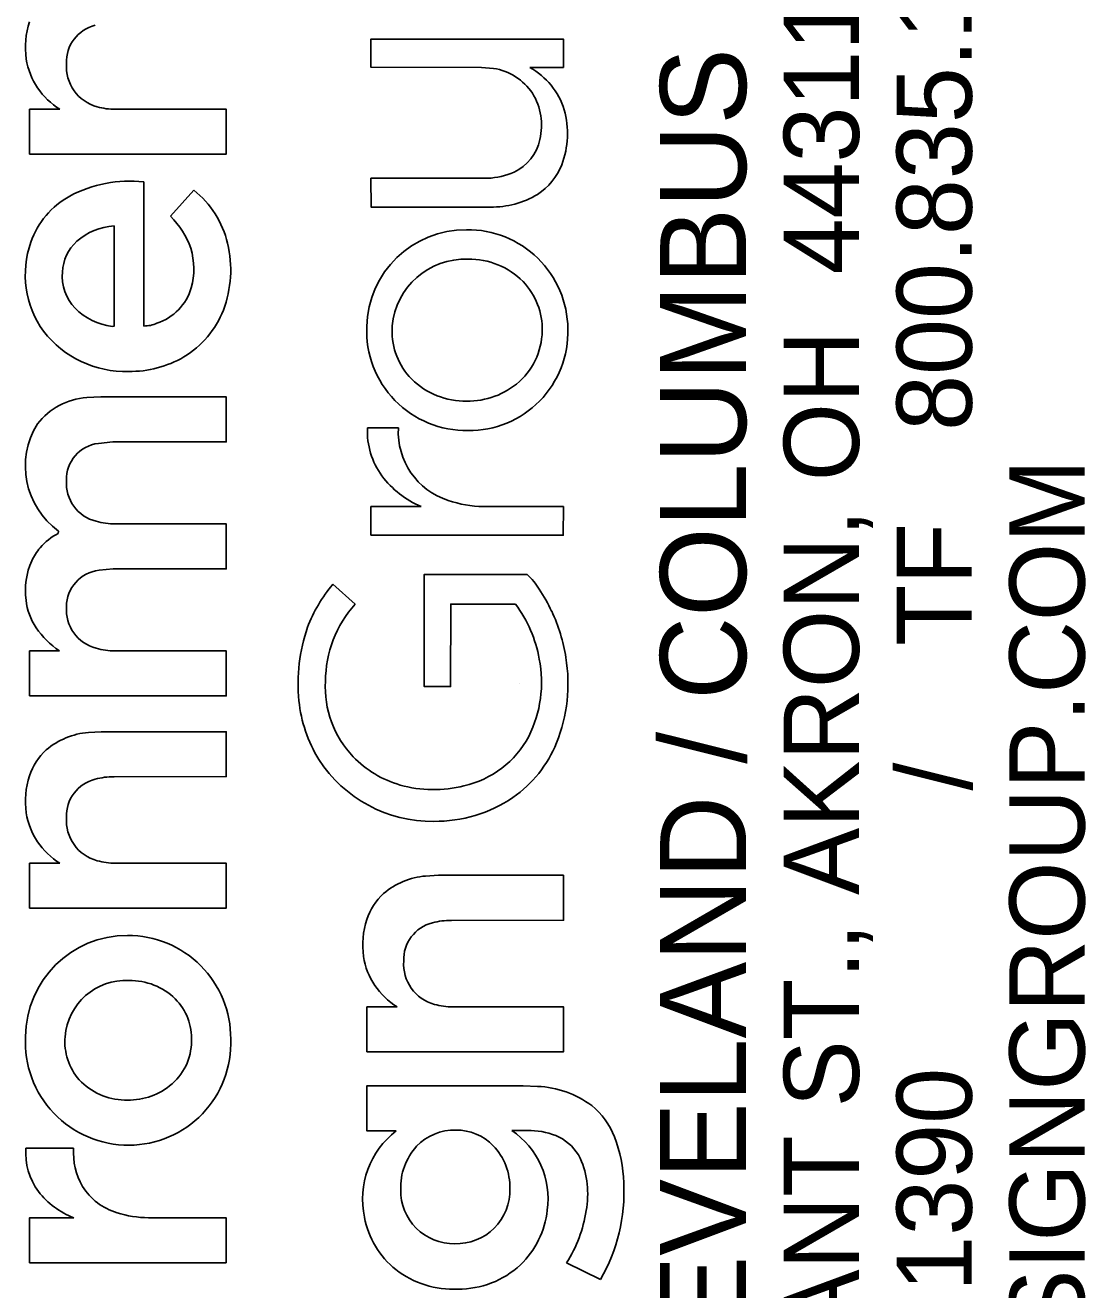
# Model space of a CAD drawing. Extents: x 0 to 34, y 0 to 22.
# Drawn here: x 32.423 to 33.125, y 3.098 to 3.936 of the extents above; entities that cross this region are included whole.
import ezdxf

# ---------------------------------------------------------------- set-up
doc = ezdxf.new("R2010")
doc.units = 0
doc.layers.add('SH_Data', color=7, linetype='Continuous')
doc.layers.add('SH_Text', color=7, linetype='Continuous')

msp = doc.modelspace()

# ---------------------------------------------------------------- linework, layer by layer
at = {"layer": 'SH_Data'}
msp.add_line((32.75, 3.5), (32.75, 3.5), dxfattribs=at)
at = {"layer": 'SH_Text'}
for p, q in [((32.65152, 3.90801), (32.65153, 3.92672)), ((32.65153, 3.92672), (32.7791, 3.92664)), ((32.7791, 3.92664), (32.77908, 3.90796)), ((32.7249, 3.90796), (32.65152, 3.90801)), ((32.7328, 3.90727), (32.7249, 3.90796)), ((32.77908, 3.90796), (32.75689, 3.90796)), ((32.42542, 3.88016), (32.44552, 3.88021)), ((32.42542, 3.85035), (32.42542, 3.88016)), ((32.48222, 3.88021), (32.55569, 3.88021)), ((32.55569, 3.88021), (32.55571, 3.85045)), ((32.55571, 3.85045), (32.42542, 3.85035)), ((32.50108, 3.83209), (32.50118, 3.73657)), ((32.65154, 3.83443), (32.72905, 3.8345)), ((32.65165, 3.81543), (32.65154, 3.83443)), ((32.51882, 3.80927), (32.53422, 3.82662)), ((32.73073, 3.81543), (32.65165, 3.81543)), ((32.48144, 3.73644), (32.48144, 3.80296)), ((32.48016, 3.73628), (32.48144, 3.73644)), ((32.46329, 3.68915), (32.47259, 3.68968)), ((32.47259, 3.68968), (32.55557, 3.68968)), ((32.55557, 3.68968), (32.55571, 3.65982)), ((32.64932, 3.66907), (32.66978, 3.66907)), ((32.48058, 3.65981), (32.47102, 3.65881)), ((32.55571, 3.65982), (32.48058, 3.65981)), ((32.65152, 3.61699), (32.68476, 3.617)), ((32.65152, 3.598), (32.65152, 3.61699)), ((32.72605, 3.61703), (32.7791, 3.61696)), ((32.7791, 3.61696), (32.77903, 3.598)), ((32.48218, 3.60553), (32.55571, 3.60548)), ((32.55571, 3.60548), (32.55571, 3.57568)), ((32.44443, 3.59922), (32.44455, 3.60072)), ((32.77903, 3.598), (32.65152, 3.598)), ((32.4809, 3.57567), (32.47143, 3.57474)), ((32.55571, 3.57568), (32.4809, 3.57567)), ((32.6868, 3.57185), (32.75516, 3.57192)), ((32.6868, 3.49778), (32.6868, 3.57185)), ((32.62636, 3.56548), (32.64114, 3.55241)), ((32.70448, 3.55241), (32.70432, 3.49775)), ((32.74737, 3.55227), (32.70448, 3.55241)), ((32.42542, 3.49152), (32.42545, 3.52138)), ((32.42545, 3.52138), (32.44515, 3.52138)), ((32.48206, 3.52138), (32.55571, 3.52136)), ((32.55571, 3.52136), (32.55571, 3.49156)), ((32.70432, 3.49775), (32.6868, 3.49778)), ((32.55571, 3.49156), (32.42542, 3.49152)), ((32.46439, 3.46736), (32.47289, 3.46783)), ((32.47289, 3.46783), (32.55571, 3.46783)), ((32.55571, 3.46783), (32.55571, 3.43804)), ((32.55571, 3.43804), (32.4814, 3.43796)), ((32.42542, 3.38066), (32.44552, 3.38071)), ((32.42542, 3.35086), (32.42542, 3.38066)), ((32.48222, 3.38071), (32.55569, 3.38071)), ((32.55569, 3.38071), (32.55571, 3.35096)), ((32.68784, 3.3722), (32.69634, 3.37266)), ((32.69634, 3.37266), (32.77916, 3.37266)), ((32.77916, 3.37266), (32.77917, 3.34287)), ((32.55571, 3.35096), (32.42542, 3.35086)), ((32.77917, 3.34287), (32.70485, 3.3428)), ((32.64888, 3.2855), (32.66897, 3.28555)), ((32.64888, 3.25569), (32.64888, 3.2855)), ((32.70568, 3.28555), (32.77915, 3.28555)), ((32.77915, 3.28555), (32.77917, 3.25579)), ((32.77917, 3.25579), (32.64888, 3.25569)), ((32.6489, 3.20336), (32.64889, 3.23322)), ((32.64889, 3.23322), (32.75236, 3.23322)), ((32.75236, 3.23322), (32.76191, 3.23285)), ((32.66836, 3.20336), (32.6489, 3.20336)), ((32.75763, 3.20356), (32.74487, 3.20361)), ((32.42299, 3.19193), (32.45454, 3.19193)), ((32.42542, 3.14577), (32.45473, 3.14579)), ((32.42542, 3.11593), (32.42542, 3.14577)), ((32.50413, 3.14581), (32.55571, 3.14573)), ((32.55571, 3.14573), (32.55565, 3.11593)), ((32.55565, 3.11593), (32.42542, 3.11593)), ((32.8036, 3.10491), (32.7812, 3.11598))]:
    msp.add_line(p, q, dxfattribs=at)
for points in [[(32.7328, 3.90727), (32.7249, 3.90796), (32.65152, 3.90801), (32.65153, 3.92672), (32.7791, 3.92664), (32.77908, 3.90796), (32.75689, 3.90796)], [(32.42542, 3.85035), (32.42542, 3.88016), (32.44552, 3.88021)], [(32.48222, 3.88021), (32.55569, 3.88021), (32.55571, 3.85045), (32.42542, 3.85035)], [(32.50108, 3.83209), (32.50118, 3.73657)], [(32.73073, 3.81543), (32.65165, 3.81543), (32.65154, 3.83443), (32.72905, 3.8345)], [(32.51882, 3.80927), (32.53422, 3.82662)], [(32.48016, 3.73628), (32.48144, 3.73644), (32.48144, 3.80296)], [(32.46329, 3.68915), (32.47259, 3.68968), (32.55557, 3.68968), (32.55571, 3.65982), (32.48058, 3.65981), (32.47102, 3.65881)], [(32.64932, 3.66907), (32.66978, 3.66907)], [(32.72605, 3.61703), (32.7791, 3.61696), (32.77903, 3.598), (32.65152, 3.598)], [(32.65152, 3.598), (32.65152, 3.61699), (32.68476, 3.617)], [(32.48218, 3.60553), (32.55571, 3.60548), (32.55571, 3.57568), (32.4809, 3.57567), (32.47143, 3.57474)], [(32.44443, 3.59922), (32.44455, 3.60072)], [(32.74737, 3.55227), (32.70448, 3.55241), (32.70432, 3.49775), (32.6868, 3.49778), (32.6868, 3.57185), (32.75516, 3.57192)], [(32.62636, 3.56548), (32.64114, 3.55241)], [(32.42542, 3.49152), (32.42545, 3.52138), (32.44515, 3.52138)], [(32.48206, 3.52138), (32.55571, 3.52136), (32.55571, 3.49156), (32.42542, 3.49152)], [(32.46439, 3.46736), (32.47289, 3.46783), (32.55571, 3.46783), (32.55571, 3.43804), (32.4814, 3.43796)], [(32.42542, 3.35086), (32.42542, 3.38066), (32.44552, 3.38071)], [(32.48222, 3.38071), (32.55569, 3.38071), (32.55571, 3.35096), (32.42542, 3.35086)], [(32.68784, 3.3722), (32.69634, 3.37266), (32.77916, 3.37266), (32.77917, 3.34287), (32.70485, 3.3428)], [(32.64888, 3.25569), (32.64888, 3.2855), (32.66897, 3.28555)], [(32.70568, 3.28555), (32.77915, 3.28555), (32.77917, 3.25579), (32.64888, 3.25569)], [(32.66836, 3.20336), (32.6489, 3.20336), (32.64889, 3.23322), (32.75236, 3.23322), (32.76191, 3.23285)], [(32.75763, 3.20356), (32.74487, 3.20361)], [(32.42299, 3.19193), (32.45454, 3.19193)], [(32.50413, 3.14581), (32.55571, 3.14573), (32.55565, 3.11593), (32.42542, 3.11593)], [(32.42542, 3.11593), (32.42542, 3.14577), (32.45473, 3.14579)], [(32.8036, 3.10491), (32.7812, 3.11598)]]:
    msp.add_lwpolyline(points, dxfattribs=at)
for centre, radius, start, end in [((32.47872, 3.92108), 0.05602, 162.27398, 187.79173), ((32.47872, 3.92108), 0.05602, 162.27398, 187.79173), ((32.47482, 3.91155), 0.02498, 103.68683, 182.21395), ((32.47482, 3.91155), 0.02498, 103.68683, 182.21395), ((32.47027, 3.9209), 0.04763, 188.96462, 238.69865), ((32.47027, 3.9209), 0.04763, 188.96462, 238.69865), ((32.47735, 3.90846), 0.02757, 175.58441, 255.13816), ((32.47735, 3.90846), 0.02757, 175.58441, 255.13816), ((32.72711, 3.86998), 0.03772, 33.50082, 81.32954), ((32.72711, 3.86998), 0.03772, 33.50082, 81.32954), ((32.73239, 3.86485), 0.04959, 17.62209, 60.38974), ((32.73239, 3.86485), 0.04959, 17.62209, 60.38974), ((32.72414, 3.8695), 0.04048, 346.56179, 31.75389), ((32.72414, 3.8695), 0.04048, 346.56179, 31.75389), ((32.48183, 3.92235), 0.04215, 254.08913, 270.52838), ((32.48183, 3.92235), 0.04215, 254.08913, 270.52838), ((32.72343, 3.86415), 0.05838, 339.16197, 15.61485), ((32.72343, 3.86415), 0.05838, 339.16197, 15.61485), ((32.73371, 3.86616), 0.03042, 294.63214, 348.48625), ((32.73371, 3.86616), 0.03042, 294.63214, 348.48625), ((32.72747, 3.88081), 0.04633, 271.95199, 294.08943), ((32.72747, 3.88081), 0.04633, 271.95199, 294.08943), ((32.739, 3.85901), 0.04201, 303.10391, 338.15613), ((32.739, 3.85901), 0.04201, 303.10391, 338.15613), ((32.49176, 3.74874), 0.08387, 83.62118, 118.28448), ((32.49176, 3.74874), 0.08387, 83.62118, 118.28448), ((32.47894, 3.77368), 0.05583, 118.82935, 160.62242), ((32.47894, 3.77368), 0.05583, 118.82935, 160.62242), ((32.49399, 3.7763), 0.06443, 13.53275, 51.36266), ((32.49399, 3.7763), 0.06443, 13.53275, 51.36266), ((32.7321, 3.87256), 0.05715, 268.62699, 301.47779), ((32.7321, 3.87256), 0.05715, 268.62699, 301.47779), ((32.48033, 3.77018), 0.05485, 19.0387, 45.44322), ((32.48033, 3.77018), 0.05485, 19.0387, 45.44322), ((32.4844, 3.76071), 0.04236, 94.01311, 130.88062), ((32.4844, 3.76071), 0.04236, 94.01311, 130.88062), ((32.71435, 3.73484), 0.06552, 89.48213, 178.77752), ((32.71435, 3.73484), 0.06552, 89.48213, 178.77752), ((32.71582, 3.73414), 0.06623, 0.42265, 90.7613), ((32.71582, 3.73414), 0.06623, 0.42265, 90.7613), ((32.48697, 3.77074), 0.06438, 160.52138, 215.78155), ((32.48697, 3.77074), 0.06438, 160.52138, 215.78155), ((32.47703, 3.7709), 0.02985, 132.98553, 177.1802), ((32.47703, 3.7709), 0.02985, 132.98553, 177.1802), ((32.48724, 3.77433), 0.04701, 344.60723, 17.00675), ((32.48724, 3.77433), 0.04701, 344.60723, 17.00675), ((32.48289, 3.77384), 0.0758, 339.35431, 13.37708), ((32.48289, 3.77384), 0.0758, 339.35431, 13.37708), ((32.71397, 3.73244), 0.04846, 87.68827, 175.01696), ((32.71397, 3.73244), 0.04846, 87.68827, 175.01696), ((32.71659, 3.73036), 0.05052, 44.91202, 90.75914), ((32.71659, 3.73036), 0.05052, 44.91202, 90.75914), ((32.47824, 3.76966), 0.03114, 175.00138, 223.2876), ((32.47824, 3.76966), 0.03114, 175.00138, 223.2876), ((32.49895, 3.77177), 0.03504, 288.01084, 343.55364), ((32.49895, 3.77177), 0.03504, 288.01084, 343.55364), ((32.71955, 3.73452), 0.04549, 358.32279, 43.83486), ((32.71955, 3.73452), 0.04549, 358.32279, 43.83486), ((32.48546, 3.77826), 0.04232, 225.06454, 262.79701), ((32.48546, 3.77826), 0.04232, 225.06454, 262.79701), ((32.49548, 3.76982), 0.0626, 300.94393, 338.73223), ((32.49548, 3.76982), 0.0626, 300.94393, 338.73223), ((32.50129, 3.75678), 0.02021, 269.70042, 294.87295), ((32.50129, 3.75678), 0.02021, 269.70042, 294.87295), ((32.71483, 3.7334), 0.06606, 177.53728, 270.94524), ((32.71483, 3.7334), 0.06606, 177.53728, 270.94524), ((32.71085, 3.73311), 0.0453, 175.51467, 221.42047), ((32.71085, 3.73311), 0.0453, 175.51467, 221.42047), ((32.48908, 3.77516), 0.06872, 217.74341, 271.65606), ((32.48908, 3.77516), 0.06872, 217.74341, 271.65606), ((32.71671, 3.73271), 0.06536, 269.30834, 1.67905), ((32.71671, 3.73271), 0.06536, 269.30834, 1.67905), ((32.71931, 3.73374), 0.04572, 308.90382, 359.30947), ((32.71931, 3.73374), 0.04572, 308.90382, 359.30947), ((32.49204, 3.77702), 0.07055, 269.20529, 300.33566), ((32.49204, 3.77702), 0.07055, 269.20529, 300.33566), ((32.71399, 3.73734), 0.05046, 222.66255, 268.37331), ((32.71399, 3.73734), 0.05046, 222.66255, 268.37331), ((32.71567, 3.73859), 0.05178, 266.55312, 308.67253), ((32.71567, 3.73859), 0.05178, 266.55312, 308.67253), ((32.46638, 3.64404), 0.04521, 93.91118, 142.30723), ((32.46638, 3.64404), 0.04521, 93.91118, 142.30723), ((32.47585, 3.64373), 0.05319, 148.28793, 233.9556), ((32.47585, 3.64373), 0.05319, 148.28793, 233.9556), ((32.69878, 3.66662), 0.04952, 177.16211, 216.28024), ((32.69878, 3.66662), 0.04952, 177.16211, 216.28024), ((32.71735, 3.66638), 0.04764, 176.76988, 252.15044), ((32.71735, 3.66638), 0.04764, 176.76988, 252.15044), ((32.47384, 3.63499), 0.02399, 96.75763, 181.6251), ((32.47384, 3.63499), 0.02399, 96.75763, 181.6251), ((32.70975, 3.67555), 0.06366, 216.91526, 246.88619), ((32.70975, 3.67555), 0.06366, 216.91526, 246.88619), ((32.47577, 3.63241), 0.02597, 175.81573, 256.16716), ((32.47577, 3.63241), 0.02597, 175.81573, 256.16716), ((32.7269, 3.69175), 0.07473, 251.13884, 269.34694), ((32.7269, 3.69175), 0.07473, 251.13884, 269.34694), ((32.4817, 3.65053), 0.04501, 254.34629, 270.61033), ((32.4817, 3.65053), 0.04501, 254.34629, 270.61033), ((32.4638, 3.56267), 0.04137, 117.91625, 139.24296), ((32.4638, 3.56267), 0.04137, 117.91625, 139.24296), ((32.46194, 3.56452), 0.03875, 139.52447, 154.84698), ((32.46194, 3.56452), 0.03875, 139.52447, 154.84698), ((32.47144, 3.5612), 0.04877, 156.06382, 187.3493), ((32.47144, 3.5612), 0.04877, 156.06382, 187.3493), ((32.47421, 3.55056), 0.02434, 96.5532, 179.94902), ((32.47421, 3.55056), 0.02434, 96.5532, 179.94902), ((32.72498, 3.53937), 0.04438, 30.98913, 47.16099), ((32.72498, 3.53937), 0.04438, 30.98913, 47.16099), ((32.70163, 3.50187), 0.09855, 139.79476, 159.13696), ((32.70163, 3.50187), 0.09855, 139.79476, 159.13696), ((32.67091, 3.50018), 0.11106, 25.30315, 33.96179), ((32.67091, 3.50018), 0.11106, 25.30315, 33.96179), ((32.46461, 3.55974), 0.04181, 186.5579, 213.38846), ((32.46461, 3.55974), 0.04181, 186.5579, 213.38846), ((32.69899, 3.50079), 0.07753, 138.25804, 179.70064), ((32.69899, 3.50079), 0.07753, 138.25804, 179.70064), ((32.67889, 3.50099), 0.08556, 10.07509, 36.83189), ((32.67889, 3.50099), 0.08556, 10.07509, 36.83189), ((32.47608, 3.54863), 0.02628, 175.722, 255.78627), ((32.47608, 3.54863), 0.02628, 175.722, 255.78627), ((32.6704, 3.49987), 0.11166, 8.80339, 25.33484), ((32.6704, 3.49987), 0.11166, 8.80339, 25.33484), ((32.47886, 3.57078), 0.0598, 214.70433, 235.68724), ((32.47886, 3.57078), 0.0598, 214.70433, 235.68724), ((32.7187, 3.49968), 0.11536, 161.14379, 185.62812), ((32.7187, 3.49968), 0.11536, 161.14379, 185.62812), ((32.48195, 3.56518), 0.0438, 253.66719, 270.14979), ((32.48195, 3.56518), 0.0438, 253.66719, 270.14979), ((32.68425, 3.50057), 0.08036, 333.46689, 11.03668), ((32.68425, 3.50057), 0.08036, 333.46689, 11.03668), ((32.67564, 3.49977), 0.10649, 338.28866, 9.28548), ((32.67564, 3.49977), 0.10649, 338.28866, 9.28548), ((32.68811, 3.49732), 0.06676, 176.66577, 223.6912), ((32.68811, 3.49732), 0.06676, 176.66577, 223.6912), ((32.69336, 3.49699), 0.08987, 185.50773, 212.01294), ((32.69336, 3.49699), 0.08987, 185.50773, 212.01294), ((32.46871, 3.41767), 0.04988, 94.97056, 130.22484), ((32.46871, 3.41767), 0.04988, 94.97056, 130.22484), ((32.69868, 3.49547), 0.0652, 282.88151, 331.81475), ((32.69868, 3.49547), 0.0652, 282.88151, 331.81475), ((32.69835, 3.49168), 0.08241, 305.03061, 337.67573), ((32.69835, 3.49168), 0.08241, 305.03061, 337.67573), ((32.46348, 3.42602), 0.04016, 132.22383, 161.68229), ((32.46348, 3.42602), 0.04016, 132.22383, 161.68229), ((32.69211, 3.49748), 0.08908, 212.70222, 270.71399), ((32.69211, 3.49748), 0.08908, 212.70222, 270.71399), ((32.69045, 3.50011), 0.07039, 224.02147, 253.88), ((32.69045, 3.50011), 0.07039, 224.02147, 253.88), ((32.47872, 3.42158), 0.05602, 162.27398, 187.79173), ((32.47872, 3.42158), 0.05602, 162.27398, 187.79173), ((32.47482, 3.41206), 0.02498, 103.68683, 182.21395), ((32.47482, 3.41206), 0.02498, 103.68683, 182.21395), ((32.48108, 3.39196), 0.04601, 89.60515, 105.33026), ((32.48108, 3.39196), 0.04601, 89.60515, 105.33026), ((32.69318, 3.51254), 0.08309, 254.45353, 283.9512), ((32.69318, 3.51254), 0.08309, 254.45353, 283.9512), ((32.69429, 3.49979), 0.09138, 269.3273, 304.19632), ((32.69429, 3.49979), 0.09138, 269.3273, 304.19632), ((32.47027, 3.42141), 0.04763, 188.96462, 238.69865), ((32.47027, 3.42141), 0.04763, 188.96462, 238.69865), ((32.47735, 3.40897), 0.02757, 175.58441, 255.13816), ((32.47735, 3.40897), 0.02757, 175.58441, 255.13816), ((32.48183, 3.42286), 0.04215, 254.08913, 270.52838), ((32.48183, 3.42286), 0.04215, 254.08913, 270.52838), ((32.69216, 3.32251), 0.04988, 94.97056, 130.22484), ((32.69216, 3.32251), 0.04988, 94.97056, 130.22484), ((32.68694, 3.33085), 0.04016, 132.22383, 161.68229), ((32.68694, 3.33085), 0.04016, 132.22383, 161.68229), ((32.70217, 3.32642), 0.05602, 162.27398, 187.79173), ((32.70217, 3.32642), 0.05602, 162.27398, 187.79173), ((32.70453, 3.29679), 0.04601, 89.60515, 105.33026), ((32.70453, 3.29679), 0.04601, 89.60515, 105.33026), ((32.69828, 3.31689), 0.02498, 103.68683, 182.21395), ((32.69828, 3.31689), 0.02498, 103.68683, 182.21395), ((32.49014, 3.26543), 0.0674, 89.84756, 179.64047), ((32.49014, 3.26543), 0.0674, 89.84756, 179.64047), ((32.49057, 3.26474), 0.0681, 359.54009, 90.21138), ((32.49057, 3.26474), 0.0681, 359.54009, 90.21138), ((32.69372, 3.32624), 0.04763, 188.96462, 238.69865), ((32.69372, 3.32624), 0.04763, 188.96462, 238.69865), ((32.7008, 3.31381), 0.02757, 175.58441, 255.13816), ((32.7008, 3.31381), 0.02757, 175.58441, 255.13816), ((32.48923, 3.26263), 0.0404, 87.04809, 175.57259), ((32.48923, 3.26263), 0.0404, 87.04809, 175.57259), ((32.49204, 3.25999), 0.04299, 45.84264, 90.98008), ((32.49204, 3.25999), 0.04299, 45.84264, 90.98008), ((32.49458, 3.26421), 0.03821, 357.88569, 44.15902), ((32.49458, 3.26421), 0.03821, 357.88569, 44.15902), ((32.70529, 3.32769), 0.04215, 254.08913, 270.52838), ((32.70529, 3.32769), 0.04215, 254.08913, 270.52838), ((32.49083, 3.26209), 0.06819, 176.8344, 270.40384), ((32.49083, 3.26209), 0.06819, 176.8344, 270.40384), ((32.48729, 3.2625), 0.03848, 175.15378, 221.14706), ((32.48729, 3.2625), 0.03848, 175.15378, 221.14706), ((32.49123, 3.26139), 0.06749, 270.06243, 2.37759), ((32.49123, 3.26139), 0.06749, 270.06243, 2.37759), ((32.49446, 3.26318), 0.0383, 308.28936, 359.43468), ((32.49446, 3.26318), 0.0383, 308.28936, 359.43468), ((32.48919, 3.26607), 0.04228, 223.09994, 268.80895), ((32.48919, 3.26607), 0.04228, 223.09994, 268.80895), ((32.49096, 3.2679), 0.04418, 266.56515, 308.06078), ((32.49096, 3.2679), 0.04418, 266.56515, 308.06078), ((32.75907, 3.16789), 0.06503, 53.40344, 87.49062), ((32.75907, 3.16789), 0.06503, 53.40344, 87.49062), ((32.76517, 3.18039), 0.05141, 21.60748, 50.5577), ((32.76517, 3.18039), 0.05141, 21.60748, 50.5577), ((32.70292, 3.15813), 0.05692, 127.37482, 192.22468), ((32.70292, 3.15813), 0.05692, 127.37482, 192.22468), ((32.70693, 3.16927), 0.0346, 88.47302, 136.42562), ((32.70693, 3.16927), 0.0346, 88.47302, 136.42562), ((32.70814, 3.16963), 0.03424, 44.27195, 90.47623), ((32.70814, 3.16963), 0.03424, 44.27195, 90.47623), ((32.71421, 3.15829), 0.05472, 352.1125, 55.92295), ((32.71421, 3.15829), 0.05472, 352.1125, 55.92295), ((32.75666, 3.15725), 0.04633, 65.01687, 88.8011), ((32.75666, 3.15725), 0.04633, 65.01687, 88.8011), ((32.46616, 3.18882), 0.04329, 175.87313, 216.34747), ((32.46616, 3.18882), 0.04329, 175.87313, 216.34747), ((32.50087, 3.18948), 0.04639, 176.9688, 209.60636), ((32.50087, 3.18948), 0.04639, 176.9688, 209.60636), ((32.71141, 3.16602), 0.0401, 137.46739, 182.33237), ((32.71141, 3.16602), 0.0401, 137.46739, 182.33237), ((32.70368, 3.166), 0.03996, 358.57141, 43.53765), ((32.70368, 3.166), 0.03996, 358.57141, 43.53765), ((32.7626, 3.17155), 0.03085, 26.26808, 63.80301), ((32.7626, 3.17155), 0.03085, 26.26808, 63.80301), ((32.73069, 3.16714), 0.08835, 1.15143, 21.3627), ((32.73069, 3.16714), 0.08835, 1.15143, 21.3627), ((32.73565, 3.16154), 0.05953, 349.30734, 23.43071), ((32.73565, 3.16154), 0.05953, 349.30734, 23.43071), ((32.49514, 3.18814), 0.04079, 211.94466, 253.2028), ((32.49514, 3.18814), 0.04079, 211.94466, 253.2028), ((32.70538, 3.16244), 0.11383, 329.6388, 3.25998), ((32.70538, 3.16244), 0.11383, 329.6388, 3.25998), ((32.47466, 3.19716), 0.05511, 218.09809, 248.7907), ((32.47466, 3.19716), 0.05511, 218.09809, 248.7907), ((32.70645, 3.1637), 0.03511, 178.88208, 271.08374), ((32.70645, 3.1637), 0.03511, 178.88208, 271.08374), ((32.70818, 3.16404), 0.03546, 268.27882, 1.55016), ((32.70818, 3.16404), 0.03546, 268.27882, 1.55016), ((32.70988, 3.15708), 0.05887, 313.74196, 353.8554), ((32.70988, 3.15708), 0.05887, 313.74196, 353.8554), ((32.70738, 3.16334), 0.08771, 327.31495, 351.57478), ((32.70738, 3.16334), 0.08771, 327.31495, 351.57478), ((32.50465, 3.2165), 0.07069, 252.46555, 269.57296), ((32.50465, 3.2165), 0.07069, 252.46555, 269.57296), ((32.70463, 3.15696), 0.05837, 190.75182, 231.28919), ((32.70463, 3.15696), 0.05837, 190.75182, 231.28919), ((32.70632, 3.16112), 0.06269, 232.46061, 272.59022), ((32.70632, 3.16112), 0.06269, 232.46061, 272.59022), ((32.70954, 3.15901), 0.06051, 269.6361, 312.70877), ((32.70954, 3.15901), 0.06051, 269.6361, 312.70877)]:
    msp.add_arc(centre, radius, start, end, dxfattribs=at)

# ---------------------------------------------------------------- texts
for s, height, p in [('800.835.1390', 0.0498462, (33.04966, 3.6671)), ('450 GRANT ST., AKRON, OH  44311', 0.0498462, (32.97489, 2.83738)), ('AKRON / CLEVELAND / COLUMBUS', 0.056969, (32.90012, 2.638)), ('ENVDESIGNGROUP.COM', 0.0498462, (33.12443, 2.83738)), ('TF', 0.049846, (33.04966, 3.5246)), ('/  ', 0.049846, (33.04966, 3.42884)), ('330.375.1390', 0.0498462, (33.04966, 2.83738))]:
    msp.add_text(s, height=height, rotation=90, dxfattribs=at).set_placement(p)

doc.saveas('drawing.dxf')
